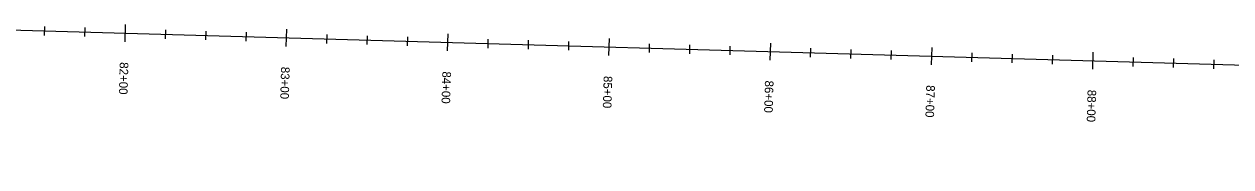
# Model space of a CAD drawing. Extents: x 2301963 to 2307911, y 760768 to 761974.
# Drawn here: x 2304930 to 2305677, y 760810 to 760898 of the extents above; entities that cross this region are included whole.
import ezdxf

# ---------------------------------------------------------------- set-up
doc = ezdxf.new("R2010")
doc.units = 0
for name, color, linetype in [('Default', 7, 'Continuous'), ('Draft_Station Labels Major', 7, 'Continuous'), ('Draft_Station Ticks Major', 7, 'Continuous'), ('Draft_Station Ticks Minor', 7, 'Continuous'), ('Geom_Secondary', 7, 'Continuous')]:
    doc.layers.add(name, color=color, linetype=linetype)

msp = doc.modelspace()

# ---------------------------------------------------------------- linework, layer by layer
at = {"layer": 'Default'}
msp.add_line((2304792.58, 760898.19), (2307901.31, 760809.5), dxfattribs=at)
at = {"layer": 'Draft_Station Ticks Major'}
for p, q in [((2304992.16, 760897.84), (2304991.86, 760887.22)), ((2305092.12, 760894.99), (2305091.82, 760884.37)), ((2305192.08, 760892.14), (2305191.78, 760881.52)), ((2305292.04, 760889.28), (2305291.74, 760878.67)), ((2305392, 760886.43), (2305391.7, 760875.82)), ((2305491.96, 760883.58), (2305491.66, 760872.96)), ((2305591.92, 760880.73), (2305591.62, 760870.11))]:
    msp.add_line(p, q, dxfattribs=at)
at = {"layer": 'Draft_Station Ticks Minor'}
for p, q in [((2304942.11, 760896.69), (2304941.95, 760891.17)), ((2304967.1, 760895.97), (2304966.94, 760890.45)), ((2305017.08, 760894.55), (2305016.92, 760889.03)), ((2305042.07, 760893.83), (2305041.91, 760888.32)), ((2305067.06, 760893.12), (2305066.9, 760887.6)), ((2305117.04, 760891.69), (2305116.88, 760886.18)), ((2305142.03, 760890.98), (2305141.87, 760885.46)), ((2305167.02, 760890.27), (2305166.86, 760884.75)), ((2305217, 760888.84), (2305216.84, 760883.33)), ((2305241.99, 760888.13), (2305241.83, 760882.61)), ((2305266.98, 760887.42), (2305266.82, 760881.9)), ((2305316.96, 760885.99), (2305316.8, 760880.47)), ((2305341.95, 760885.28), (2305341.79, 760879.76)), ((2305366.94, 760884.57), (2305366.78, 760879.05)), ((2305416.92, 760883.14), (2305416.76, 760877.62)), ((2305441.91, 760882.43), (2305441.75, 760876.91)), ((2305466.9, 760881.71), (2305466.74, 760876.2)), ((2305516.88, 760880.29), (2305516.72, 760874.77)), ((2305541.87, 760879.57), (2305541.71, 760874.06)), ((2305566.86, 760878.86), (2305566.7, 760873.34)), ((2305616.84, 760877.44), (2305616.68, 760871.92)), ((2305641.83, 760876.72), (2305641.67, 760871.21)), ((2305666.82, 760876.01), (2305666.66, 760870.49))]:
    msp.add_line(p, q, dxfattribs=at)
at = {"layer": 'Geom_Secondary'}
msp.add_line((2304792.58, 760898.19), (2307901.31, 760809.5), dxfattribs=at)

# ---------------------------------------------------------------- texts
at = {"layer": 'Draft_Station Labels Major'}
for s, p in [('82+00', (2304988.83, 760874.58)), ('83+00', (2305088.79, 760871.73)), ('84+00', (2305188.75, 760868.88)), ('85+00', (2305288.71, 760866.03)), ('86+00', (2305388.67, 760863.18)), ('87+00', (2305488.63, 760860.33)), ('88+00', (2305588.59, 760857.47))]:
    msp.add_text(s, height=5.34, rotation=268.36584, dxfattribs=at).set_placement(p)

doc.saveas('drawing.dxf')
